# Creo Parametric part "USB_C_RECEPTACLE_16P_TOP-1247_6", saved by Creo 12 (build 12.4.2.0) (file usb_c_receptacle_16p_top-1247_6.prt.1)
Units: Custom; MM, KILOGRAM, SECS

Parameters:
  PTC_WM_ITERATION = "0"
  PTC_WM_VERSION = "-.0"
  PTC_WM_LIFECYCLE_STATE = "In Work"
  PTC_WM_LIFECYCLE = "MO_CADDocument"
  PTC_WM_CREATED_BY = "Maximilian Roepper (Z0017RMS: MO)"
  PTC_WM_CREATED_ON = "18-Sep-26 11:36:42 AM"
  PTC_WM_MODIFIED_BY = "Maximilian Roepper (Z0017RMS: MO)"
  PTC_WM_MODIFIED_ON = "18-Sep-26 11:36:46 AM"
  PDMLINKNUMBER = "PDM000071454820"
  PTC_WM_NAME = "usb_c_receptacle_16p_top-1247_6.prt"
  PTC_WM_NUMBER = "PDM000071454820"

Other parameters: WEIGHT, WEIGHT_FACTOR, WEIGHT_ADD, _MASS_TEMP, _DIFF_TEMP, MC_ERRORS, SUPPLIER

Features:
  1. coordinate system
  2. datum plane "PRT_YZ"
  3. datum plane "PRT_XY"
  4. datum plane "PRT_XZ"
  5. coordinate system
  6. datum axis
  7. datum axis
  8. datum axis
  9. coordinate system
  10. imported feature
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
Other named items: PRT, SIEMENS_MO, DRW_VIEW_ORG, PRT_X, PRT_Y, PRT_Z, CS0, ROUGH_GROB

Layers: 00_STD_CSYS-KSYS, 01_STD_PLANES-EBENEN, 02_STD_AXES-ACHSEN, 03_STD_CSYS-KSYS, 24_IMPORT_FEAT-IMPORT_KE

Surfaces: 5 plane, 1 cylinder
